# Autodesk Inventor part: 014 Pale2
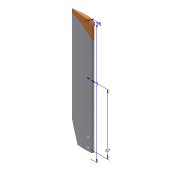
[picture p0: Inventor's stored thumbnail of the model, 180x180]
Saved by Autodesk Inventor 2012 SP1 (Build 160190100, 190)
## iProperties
Created: 2007-05
Part Number: 014 Pale2
Document SubType Name: Modeling
Designer: Yves
Material: Par défaut
Density: 1 g/cm^3
Author: Yves
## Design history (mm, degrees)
sketch "Esquisse1"
  geometry: L1 (1.26, 0)-(-21.41, 0); L2 (1.31, 1.499)-(-6.361, 1.499); A1 r 1.5 centre (1.26, 0) between (1.395, -1.494) and (1.31, 1.499); A2 r 114.85 centre (-2.525, -113.287) between (-6.361, 1.499) and (-21.41, 0); A3 r 73.88 centre (-5.236, 72.088) between (-21.41, 0) and (1.395, -1.494); 1 further point
  constraints: 6 point on circle, 4 end point, 3 centre point, 2 tangent, 1 coincident, 1 horizontal, 1 parallel, 1 point on line
  dimensions: "d0" = 73.88 radius of A3; "d1" = 114.85 radius of A2; "d2" = 1.5 radius of A1; "d3" = 1.26 distance of point (0, 0) L1.start; "d4" = 22.67 distance of A1.centre L1.end (computed from d2)
extrude "Extrusion1" new body sketch "Esquisse1" distance "d5" = 127; taper "d6" = 0 deg
sketch "Esquisse2"
  geometry: L1 (21.41, 127)-(21.41, 0); L2 (21.41, 0)-(-2.76, 0); L3 (-2.76, 0)-(-2.76, 127); L4 (-2.76, 127)-(21.41, 127); L5 (21.41, 20)-(14.131, 0); L6 (2.24, 0)-(2.24, 14); L7 (-2.76, 108.185)-(3.732, 114.678); L8 (3.732, 114.678)-(21.41, 97); L9 (-1.395, 127)-(21.41, 127) reference; L10 (21.41, 0)-(21.41, 127) reference; L11 (-1.395, 0)-(21.41, 0) reference; L12 (-1.395, 0)-(-1.395, 127) reference; L13 (-2.76, 0)-(-1.31, 0) reference; C1 r 1.05 at (2.24, 4); C2 r 1.05 at (2.24, 14); A1 r 7.5 centre (4.74, 119.5) between (4.74, 127) and (-2.76, 119.5); A2 r 25 centre (21.41, 97) between (21.41, 122) and (3.732, 114.678)
  constraints: 16 end point, 11 point on line, 4 centre point, 4 point on circle, 3 tangent, 1 equal radius, 1 perpendicular
  dimensions: "d7" = 7.5 radius of A1; "d10" = 20 deg angle of L1 L5; "d11" = 20 vertical distance of L5.start L5.end; "d14" = 2.1 diameter of C1; "d15" = 4 distance from line of L2 C1.centre; "d16" = 10 distance of L6.end C1.centre; "d17" = 5 distance between parallel lines of L3 L6; "d20" = 45 deg angle of L3 L7; "d21" = 25 radius of A2; "d22" = 5 distance from line of L4 A2.start
  node "Boucle projetée1"
extrude "Extrusion2" cut sketch "Esquisse2" stored distance "d8" = 254; taper "d9" = 0 deg
extrude "Extrusion3" cut sketch "Esquisse2" stored distance "d12" = 254; taper "d13" = 0 deg
extrude "Extrusion4" cut sketch "Esquisse2" stored distance "d18" = 254; taper "d19" = 0 deg
feature "Scission1"
sketch "Esquisse3"
  geometry: L1 (0, 0)-(7.671, 0) reference; L2 (0, 0)-(0, -116.963) reference; L3 (4.121, 0)-(4.121, -124.659); C1 r 0.5 at (4.121, -124.659); C2 r 0.5 at (4.121, -67); 3 further points; 2 other entities
  constraints: 2 centre point, 2 end point, 2 point on line, 1 coincident, 1 parallel, 2 other
  dimensions: "d24" = 1 diameter of C1; "d25" = 1 diameter of C2; "d26" = 67 distance of L3.start C2.centre; "d28" = 134 vertical distance of C1.centre point (4.628, 9.341)
extrude "Extrusion5" cut sketch "Esquisse3" distance "d29" = 10; taper "d30" = 0 deg
node "Solide1"
node "Corps solides"
node "Corps surfaciques"
node "Référence1"
node "Référence2"
